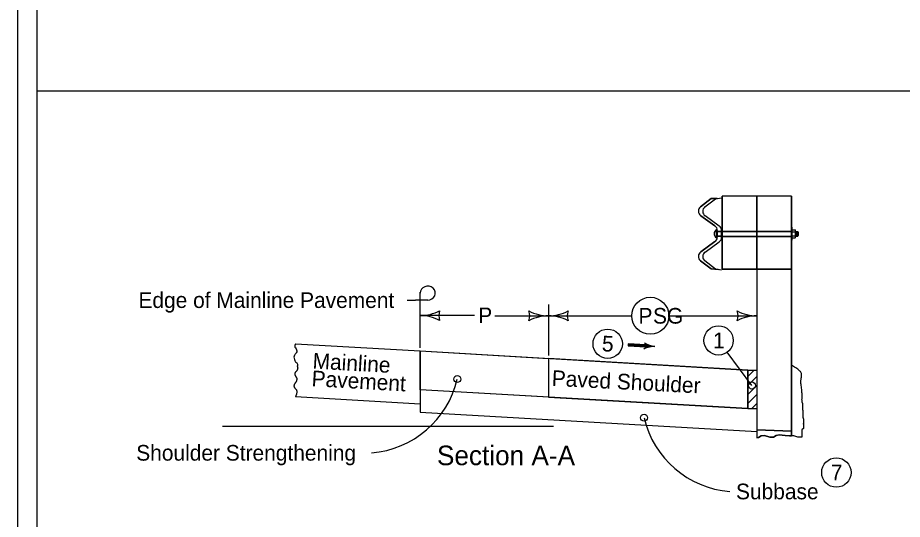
# Model space of a CAD drawing. Extents: x 10133 to 81668, y 7924 to 12229.
# Drawn here: x 10133 to 11037, y 8919 to 9431 of the extents above; entities that cross this region are included whole.
import ezdxf

# ---------------------------------------------------------------- set-up
doc = ezdxf.new("R2010")
doc.units = 0
for name, color, linetype in [('Cell', 7, 'Continuous'), ('dsnTextFinalPlan', 7, 'Continuous'), ('Level 1', 7, 'Continuous'), ('Level 12', 7, 'Continuous'), ('Level 4', 7, 'Continuous'), ('Level 5', 7, 'Continuous'), ('Level 6', 7, 'Continuous'), ('SheetBorder', 7, 'Continuous')]:
    doc.layers.add(name, color=color, linetype=linetype)

msp = doc.modelspace()

# ---------------------------------------------------------------- linework, layer by layer
at = {"layer": 'Cell'}
for p, q in [((10831.21, 9229.02), (10845.72, 9218.6)), ((10845.72, 9202.53), (10831.21, 9192.11))]:
    msp.add_line(p, q, dxfattribs=at)
for points in [[(10888.5, 9213.22), (10888.5, 9248.9), (10852.96, 9248.9), (10852.96, 9213.22), (10852.96, 9213.22), (10888.5, 9213.22)], [(10924.05, 9213.22), (10924.05, 9217.22), (10924.05, 9248.9), (10888.5, 9248.9), (10888.5, 9213.22), (10924.05, 9213.22)], [(10835.46, 9237.92), (10835.45, 9237.91), (10846.22, 9246.31), (10848.11, 9246.65), (10841.78, 9246.53), (10831.02, 9238.14)], [(10850.16, 9218.38), (10850.19, 9218.36), (10835.63, 9228.82), (10835.66, 9228.8)], [(10848.11, 9213.97), (10848.11, 9212.89), (10852.56, 9212.89), (10852.56, 9213.75), (10852.56, 9213.75)], [(10852.96, 9212.89), (10852.96, 9208.22), (10852.96, 9208.22), (10888.5, 9208.22), (10888.5, 9212.89), (10852.96, 9212.89), (10852.96, 9212.89)], [(10924.05, 9208.22), (10924.05, 9212.89), (10888.5, 9212.89), (10888.5, 9208.22), (10924.05, 9208.22)], [(10835.66, 9191.89), (10835.63, 9191.87), (10850.19, 9202.33), (10850.16, 9202.31)], [(10852.56, 9206.94), (10852.56, 9206.94), (10852.56, 9208.22), (10848.12, 9208.22), (10848.12, 9207.16), (10848.12, 9208.22), (10848.11, 9208.22), (10848.11, 9207.16)], [(10852.96, 9207.89), (10852.96, 9174.25), (10888.5, 9174.25), (10888.5, 9207.89), (10852.96, 9207.89)], [(10924.05, 9174.25), (10924.05, 9203.89), (10924.05, 9207.89), (10888.5, 9207.89), (10888.5, 9174.25), (10924.05, 9174.25)], [(10831.02, 9182.99), (10841.78, 9174.6), (10848.88, 9173.91), (10846.22, 9174.38), (10835.45, 9182.79), (10835.46, 9182.77)], [(10924.05, 9008.91), (10924.05, 9174.25), (10888.5, 9174.25), (10888.5, 9071.28), (10888.5, 9064.59), (10888.5, 9064.59), (10888.5, 9064.59), (10888.5, 9055.36), (10888.5, 9055.36), (10888.5, 9055.36), (10888.5, 9046.22), (10888.5, 9046.22), (10888.5, 9046.22), (10888.5, 9039.29), (10888.5, 9010.07), (10924.05, 9008.91)], [(10924.05, 9008.91), (10888.5, 9010.07), (10888.5, 9002.02), (10890.31, 9002.27), (10893.07, 9003.86), (10896.36, 9004.39), (10901.97, 9002.8), (10905.68, 9002.58), (10908.33, 9004.39), (10911.41, 9005.02), (10917.66, 9004.28), (10921.9, 9003.86), (10924.05, 9003.86), (10924.05, 9008.91)]]:
    msp.add_lwpolyline(points, dxfattribs=at)
msp.add_lwpolyline([(10852.56, 9212.89), (10848.11, 9212.89), (10848.11, 9209.43), (10848.12, 9210.56), (10848.12, 9208.22), (10852.56, 9208.22)], close=True, dxfattribs=at)
for centre, start, end in [((10834.49, 9233.65), 127.75002, 234.69086), ((10838.94, 9233.43), 127.75002, 234.69086), ((10842.44, 9213.97), 0, 54.69099), ((10846.88, 9213.75), 0, 54.69099), ((10842.44, 9207.16), 305.30901, 0), ((10846.88, 9206.94), 305.30901, 0), ((10834.49, 9187.48), 125.30914, 232.24998), ((10838.94, 9187.26), 125.30914, 232.24998)]:
    msp.add_arc(centre, 5.68, start, end, dxfattribs=at)
at = {"layer": 'dsnTextFinalPlan'}
for p, q in [((10846.22, 9246.31), (10852.56, 9247.43)), ((10924.05, 9248.9), (10852.96, 9248.9)), ((10852.96, 9174.25), (10852.96, 9248.9)), ((10888.5, 9174.25), (10888.5, 9248.9)), ((10924.05, 9248.9), (10924.05, 9003.86)), ((10831.02, 9238.14), (10841.78, 9246.53)), ((10835.45, 9237.91), (10846.22, 9246.31)), ((10841.78, 9246.53), (10848.11, 9246.65)), ((10845.72, 9218.6), (10831.21, 9229.02)), ((10850.19, 9218.36), (10835.63, 9228.82)), ((10847.34, 9206.5), (10847.34, 9214.58)), ((10847.34, 9212.89), (10852.77, 9212.89)), ((10848.12, 9207.16), (10848.11, 9213.97)), ((10848.29, 9212.89), (10852.96, 9212.89)), ((10852.56, 9210.35), (10852.56, 9213.75)), ((10852.96, 9213.22), (10924.05, 9213.22)), ((10852.96, 9212.89), (10924.05, 9212.89)), ((10924.05, 9217.19), (10924.73, 9217.19)), ((10924.73, 9203.86), (10924.73, 9217.19)), ((10924.73, 9214.57), (10927.7, 9214.57)), ((10924.73, 9212.55), (10927.7, 9212.55)), ((10928.06, 9207.5), (10928.06, 9213.56)), ((10928.06, 9212.86), (10930.43, 9212.86)), ((10928.95, 9212.86), (10928.95, 9208.19)), ((10929.69, 9212.86), (10929.69, 9208.19)), ((10930.43, 9212.86), (10930.88, 9212.33)), ((10930.43, 9212.86), (10930.43, 9208.19)), ((10930.88, 9212.33), (10930.88, 9208.73)), ((10831.21, 9192.11), (10845.72, 9202.53)), ((10835.63, 9191.87), (10850.19, 9202.33)), ((10847.34, 9208.22), (10852.96, 9208.22)), ((10848.11, 9207.16), (10848.12, 9210.56)), ((10848.12, 9210.56), (10848.12, 9207.16)), ((10852.56, 9206.94), (10852.56, 9210.35)), ((10852.56, 9210.35), (10852.56, 9206.94)), ((10852.95, 9207.89), (10924.05, 9207.89)), ((10852.96, 9208.22), (10924.05, 9208.22)), ((10924.05, 9203.86), (10924.73, 9203.86)), ((10924.73, 9208.51), (10927.7, 9208.51)), ((10924.73, 9206.49), (10927.7, 9206.49)), ((10928.06, 9208.19), (10930.43, 9208.19)), ((10930.88, 9208.73), (10930.43, 9208.19)), ((10841.78, 9174.6), (10831.02, 9182.99)), ((10846.22, 9174.38), (10835.45, 9182.79)), ((10848.88, 9173.91), (10841.78, 9174.6)), ((10852.56, 9173.26), (10846.22, 9174.38)), ((10888.5, 9174.25), (10852.96, 9174.25)), ((10888.5, 9174.25), (10888.5, 9002.02)), ((10416.65, 9098.18), (10544.11, 9090.77)), ((10544.11, 9090.77), (10544.11, 9036.76)), ((10544.11, 9090.77), (10879.25, 9071.28)), ((10675.49, 9083.13), (10675.49, 9043.6)), ((10879.25, 9071.28), (10675.49, 9083.13)), ((10675.49, 9083.13), (10675.49, 9043.6)), ((10879.25, 9064.54), (10885.99, 9071.28)), ((10879.25, 9064.54), (10885.99, 9071.28)), ((10879.25, 9064.54), (10885.99, 9071.28)), ((10879.25, 9064.54), (10885.99, 9071.28)), ((10879.25, 9071.28), (10888.49, 9071.28)), ((10879.25, 9071.28), (10879.25, 9031.85)), ((10879.25, 9031.85), (10879.25, 9071.28)), ((10879.25, 9055.35), (10888.49, 9064.59)), ((10879.25, 9055.35), (10888.49, 9064.59)), ((10879.25, 9055.35), (10888.49, 9064.59)), ((10879.25, 9055.35), (10888.49, 9064.59)), ((10934.1, 9064.52), (10934.1, 9064.52)), ((10879.25, 9031.85), (10544.11, 9051.17)), ((10879.25, 9046.13), (10888.49, 9055.36)), ((10879.25, 9046.13), (10888.49, 9055.36)), ((10879.25, 9046.13), (10888.49, 9055.36)), ((10879.25, 9046.13), (10888.49, 9055.36)), ((10416.68, 9044.17), (10544.11, 9036.76)), ((10675.49, 9043.6), (10879.25, 9031.85)), ((10879.25, 9036.9), (10888.49, 9046.14)), ((10544.11, 9036.76), (10544.11, 9028.34)), ((10879.25, 9031.85), (10888.49, 9031.85)), ((10883.35, 9031.85), (10888.49, 9036.99)), ((10544.11, 9028.34), (10888.5, 9008.48)), ((10342.06, 9013.93), (10680.56, 9013.93))]:
    msp.add_line(p, q, dxfattribs=at)
for points in [[(10927.76, 9212.55), (10927.83, 9212.59), (10927.91, 9212.7), (10927.99, 9212.92), (10928.05, 9213.2), (10928.05, 9211.26), (10927.99, 9211.77), (10927.94, 9212.14), (10927.82, 9212.46), (10927.76, 9212.55), (10927.82, 9212.56), (10927.92, 9212.7), (10928.01, 9212.93), (10928.03, 9213.08), (10928.03, 9211.55), (10927.96, 9212.04), (10927.9, 9212.3), (10927.8, 9212.53), (10927.83, 9212.54), (10927.97, 9212.76), (10928.01, 9212.91), (10928.01, 9211.8), (10927.82, 9212.52), (10927.99, 9212.79), (10927.99, 9211.94), (10927.85, 9212.5), (10927.97, 9212.72), (10927.98, 9212.08), (10927.87, 9212.49), (10927.96, 9212.66), (10927.96, 9212.25), (10927.89, 9212.47), (10927.94, 9212.59), (10927.94, 9212.38), (10927.91, 9212.46), (10927.92, 9212.5)], [(10928.05, 9207.82), (10928, 9208.09), (10927.96, 9208.26), (10927.87, 9208.42), (10927.75, 9208.51), (10927.83, 9208.61), (10927.91, 9208.83), (10927.97, 9209.14), (10928.05, 9209.89), (10928.05, 9207.82), (10928.03, 9207.96), (10927.99, 9208.17), (10927.91, 9208.39), (10927.79, 9208.5), (10927.83, 9208.58), (10927.89, 9208.73), (10927.99, 9209.23), (10928.03, 9209.61), (10928.03, 9208.01), (10928, 9208.13), (10927.96, 9208.29), (10927.83, 9208.5), (10927.88, 9208.67), (10927.96, 9209), (10928.02, 9209.33), (10928.01, 9208.16), (10927.97, 9208.29), (10927.86, 9208.49), (10927.9, 9208.7), (10927.96, 9208.96), (10927.99, 9209.13), (10927.99, 9208.27), (10927.93, 9208.38), (10927.88, 9208.49), (10927.97, 9208.95), (10927.97, 9208.35), (10927.9, 9208.49), (10927.95, 9208.78), (10927.95, 9208.43), (10927.92, 9208.5), (10927.93, 9208.6), (10927.93, 9208.52)], [(10934.57, 9040.67), (10934.51, 9040.4), (10934.51, 9040.21), (10934.51, 9040.01), (10934.51, 9039.82), (10934.51, 9039.62), (10934.51, 9039.43), (10934.51, 9039.13), (10934.51, 9038.94), (10934.61, 9038.64), (10934.71, 9038.35), (10934.9, 9038.16), (10934.9, 9037.96), (10935, 9037.76), (10935, 9037.57), (10935, 9037.37), (10935.1, 9037.28), (10935.1, 9037.08), (10935.1, 9036.89), (10935.1, 9036.69), (10935.1, 9036.49), (10935.1, 9036.3), (10935.1, 9036.01), (10935.1, 9035.71), (10935.1, 9035.52), (10935.1, 9035.22), (10935.1, 9035.03), (10935.1, 9034.83), (10935.2, 9034.74), (10935.2, 9034.54), (10935.2, 9034.34), (10935.2, 9034.15), (10935.2, 9033.95), (10935.2, 9033.76), (10935.2, 9033.56), (10935.2, 9033.37), (10935.2, 9033.17), (10935.2, 9032.98), (10935.2, 9032.78), (10935.2, 9032.59), (10935.2, 9032.39), (10935.2, 9032.2), (10935.2, 9032), (10935.2, 9031.8), (10935.2, 9031.61), (10935.2, 9031.41), (10935.2, 9031.22), (10935.29, 9031.12), (10935.29, 9030.93), (10935.29, 9030.73), (10935.39, 9030.63), (10935.39, 9030.44), (10935.39, 9030.24), (10935.49, 9030.14), (10935.49, 9029.95), (10935.49, 9029.75), (10935.49, 9029.56), (10935.49, 9029.26), (10935.59, 9028.97), (10935.59, 9028.78), (10935.59, 9028.58), (10935.59, 9028.38), (10935.59, 9028.19), (10935.59, 9027.99), (10935.59, 9027.8), (10935.59, 9027.6), (10935.59, 9027.41), (10935.59, 9027.21), (10935.59, 9027.02), (10935.59, 9026.82), (10935.59, 9026.63), (10935.59, 9026.43), (10935.59, 9026.24), (10935.59, 9026.04), (10935.59, 9025.84), (10935.59, 9025.65), (10935.59, 9025.45), (10935.59, 9025.26), (10935.59, 9025.06), (10935.59, 9024.87), (10935.59, 9024.67), (10935.59, 9024.48), (10935.59, 9024.28), (10935.59, 9024.09), (10935.59, 9023.89), (10935.59, 9023.69), (10935.59, 9023.5), (10935.59, 9023.3), (10935.68, 9023.21), (10935.68, 9022.91), (10935.68, 9022.72), (10935.78, 9022.52), (10935.88, 9022.23), (10935.88, 9022.03), (10935.98, 9021.94), (10935.98, 9021.74), (10936.07, 9021.64), (10936.17, 9021.55), (10936.17, 9021.35), (10936.17, 9021.15), (10936.17, 9020.96), (10936.27, 9020.86), (10936.27, 9020.67), (10936.27, 9020.47), (10936.27, 9020.28), (10936.27, 9020.08), (10936.27, 9019.88), (10936.27, 9019.69), (10936.27, 9019.49), (10936.27, 9019.3), (10936.27, 9019.1), (10936.27, 9018.91), (10936.27, 9018.71), (10936.27, 9018.52), (10936.27, 9018.32), (10936.27, 9018.13), (10936.27, 9017.93), (10936.27, 9017.73), (10936.27, 9017.54), (10936.27, 9017.34), (10936.27, 9017.15), (10936.27, 9016.95), (10936.27, 9016.76), (10936.27, 9016.56), (10936.27, 9016.37), (10936.27, 9016.17), (10936.27, 9015.98), (10936.27, 9015.98), (10936.27, 9016.27), (10936.27, 9016.46), (10936.27, 9016.66), (10936.27, 9016.46), (10936.27, 9016.27), (10936.27, 9016.07), (10936.27, 9015.88), (10936.27, 9015.68), (10936.27, 9015.49), (10936.27, 9015.29), (10936.27, 9015.1), (10936.27, 9014.9), (10936.27, 9014.71), (10936.27, 9014.51), (10936.27, 9014.32), (10936.27, 9014.12), (10936.27, 9013.92), (10936.27, 9013.73), (10936.17, 9013.63), (10936.17, 9013.44), (10936.17, 9013.24), (10936.17, 9013.05), (10936.17, 9012.85), (10936.17, 9012.65), (10936.17, 9012.46), (10936.17, 9012.26), (10936.17, 9012.07), (10936.17, 9011.87), (10936.17, 9011.68), (10936.07, 9011.58), (10935.98, 9011.38), (10935.88, 9011.29), (10935.78, 9011.19), (10935.68, 9011.09), (10935.49, 9010.99), (10935.29, 9010.99), (10935.2, 9010.9), (10935.1, 9010.8), (10935, 9010.7), (10934.8, 9010.6), (10934.71, 9010.5), (10934.71, 9010.31), (10934.61, 9010.21), (10934.61, 9010.02), (10934.61, 9009.82), (10934.61, 9009.63), (10934.61, 9002.81)], [(10934.74, 9002.81), (10930.59, 9002.69), (10926.46, 9003.86), (10921.9, 9003.86), (10917.66, 9004.28), (10911.41, 9005.02), (10908.33, 9004.39), (10905.68, 9002.58), (10901.97, 9002.8), (10896.36, 9004.39), (10893.07, 9003.86), (10890.31, 9002.27), (10888.5, 9002.02)]]:
    msp.add_lwpolyline(points, dxfattribs=at)
msp.add_lwpolyline([(10675.49, 9043.6), (10544.11, 9051.17), (10544.11, 9090.77), (10675.49, 9083.13)], close=True, dxfattribs=at)
for centre, radius, start, end in [((10834.49, 9233.65), 5.68, 127.75002, 234.69086), ((10838.94, 9233.43), 5.68, 127.75002, 234.69086), ((10849.42, 9210.55), 4.54, 117.20289, 242.8461), ((10842.44, 9213.97), 5.68, 360, 54.69099), ((10846.88, 9213.75), 5.68, 360, 54.69099), ((10842.44, 9207.16), 5.68, 305.30901, 0), ((10846.88, 9206.94), 5.68, 305.30901, 0), ((10834.49, 9187.48), 5.68, 125.30914, 232.24998), ((10838.94, 9187.26), 5.68, 125.30914, 232.24998)]:
    msp.add_arc(centre, radius, start, end, dxfattribs=at)
for centre in [(10927.7, 9213.56), (10927.7, 9207.5)]:
    msp.add_ellipse(centre, major_axis=(0, -1.01), ratio=0.362258, start_param=6.283156, end_param=9.424748, dxfattribs=at)
for points in [[(10416.65, 9098.18), (10416.15, 9094.58), (10417.19, 9093.08), (10418.05, 9090.78), (10417.45, 9088.72), (10415.54, 9086.34), (10415.02, 9084.44), (10415.54, 9082.15), (10416.41, 9079.77), (10417.45, 9079.06), (10418.83, 9076.52), (10418.82, 9075.69)], [(10416.86, 9058.57), (10417.07, 9058.82), (10417.27, 9059.08), (10417.62, 9059.64), (10417.9, 9060.23), (10418.02, 9060.54), (10418.12, 9060.85), (10418.25, 9061.47), (10418.3, 9062.09), (10418.25, 9062.68), (10418.19, 9062.96), (10418.16, 9063.09), (10418.11, 9063.22), (10417.9, 9063.6), (10417.62, 9063.96), (10417.32, 9064.33), (10417.07, 9064.73), (10416.93, 9065.01), (10416.79, 9065.29), (10416.53, 9065.87), (10416.33, 9066.44), (10416.26, 9066.73), (10416.2, 9067.02), (10416.19, 9067.15), (10416.19, 9067.28), (10416.34, 9068.06), (10416.55, 9068.57), (10416.81, 9069.08), (10417.25, 9069.72), (10417.77, 9070.27), (10418.29, 9070.81), (10418.52, 9071.12), (10418.72, 9071.46), (10418.92, 9071.93), (10419.08, 9072.41), (10419.18, 9072.88), (10419.22, 9073.12), (10419.23, 9073.24), (10419.24, 9073.36), (10419.19, 9073.87), (10419.04, 9074.38), (10418.99, 9074.51), (10418.93, 9074.64), (10418.88, 9074.76), (10418.86, 9074.9), (10418.82, 9075.69)], [(10934.57, 9040.67), (10934.89, 9043.58), (10934.67, 9048.45), (10934.23, 9054.2), (10933.56, 9058.62), (10933.78, 9061.93), (10934.23, 9066.13), (10933.56, 9069.23), (10931.35, 9071.22), (10929.36, 9072.99), (10927.15, 9074.1), (10924.94, 9075.42), (10924.06, 9076.09)], [(10416.86, 9058.57), (10416.64, 9058.34), (10416.4, 9058.1), (10416.16, 9057.86), (10415.98, 9057.59), (10415.84, 9057.31), (10415.7, 9057.02), (10415.44, 9056.45), (10415.33, 9056.17), (10415.23, 9055.88), (10415.16, 9055.59), (10415.13, 9055.44), (10415.11, 9055.3), (10415.12, 9054.78), (10415.25, 9054.26), (10415.46, 9053.75), (10415.72, 9053.24), (10416.16, 9052.6), (10416.68, 9052.05), (10417.2, 9051.51), (10417.43, 9051.2), (10417.63, 9050.86), (10418.03, 9049.91), (10418.14, 9049.44), (10418.15, 9048.96), (10418.11, 9048.67), (10418.06, 9048.38), (10418.01, 9048.1), (10417.94, 9047.81), (10417.63, 9046.66), (10417.45, 9046.05), (10417.25, 9045.45), (10417.03, 9044.86), (10416.9, 9044.57), (10416.76, 9044.29), (10416.68, 9044.17)]]:
    msp.add_spline(points, degree=3, dxfattribs=at)
at = {"layer": 'Level 1'}
msp.add_line((10152.18, 9924.36), (10152.18, 8314.36), dxfattribs=at)
at = {"layer": 'Level 12'}
for centre, radius in [((10735.98, 9098.17), 15), ((10849.44, 9101.57), 15), ((10883.56, 9055.46), 3.58), ((10969.88, 8966.52), 15)]:
    msp.add_circle(centre, radius, dxfattribs=at)
at = {"layer": 'Level 4'}
for p, q in [((12307.76, 9356.36), (10152.18, 9356.36)), ((10883.56, 9055.46), (10858.18, 9089.38))]:
    msp.add_line(p, q, dxfattribs=at)
for centre in [(10582.12, 9062.01), (10773.25, 9022.49)]:
    msp.add_circle(centre, 3.54, dxfattribs=at)
at = {"layer": 'Level 5'}
for p, q in [((10675.49, 9138.3), (10675.49, 9086.27)), ((10599.61, 9126.91), (10544.13, 9126.91)), ((10620.73, 9126.69), (10675.49, 9126.69)), ((10675.49, 9126.69), (10760.66, 9126.69)), ((10798.53, 9126.69), (10888.5, 9126.69))]:
    msp.add_line(p, q, dxfattribs=at)
msp.add_circle((10779.6, 9126.69), 18.93, dxfattribs=at)
for centre, radius, start, end in [((10544.13, 9169.41), 42.5, 270, 298.07249), ((10579.77, 9126.91), 16.42, 162.26665, 197.73335), ((10639.85, 9126.69), 16.42, 342.26665, 17.73335), ((10675.49, 9169.19), 42.5, 241.92751, 270), ((10675.49, 9169.19), 42.5, 270, 298.07249), ((10711.12, 9126.69), 16.42, 162.26665, 197.73335), ((10852.87, 9126.69), 16.42, 342.26665, 17.73335), ((10888.5, 9169.19), 42.5, 241.92751, 270), ((10544.13, 9084.41), 42.5, 61.92751, 90), ((10675.49, 9084.19), 42.5, 90, 118.07249), ((10675.49, 9084.19), 42.5, 61.92751, 90), ((10888.5, 9084.19), 42.5, 90, 118.07249), ((10486.89, 9084.13), 97.76, 274.44201, 346.92302), ((10868.48, 9044.61), 97.76, 193.07698, 265.55799)]:
    msp.add_arc(centre, radius, start, end, dxfattribs=at)
at = {"layer": 'Level 6'}
for p, q in [((10544.11, 9129.85), (10544.11, 9150.71)), ((10530.74, 9142.7), (10539.43, 9142.7)), ((10551.92, 9142.7), (10539.43, 9142.7)), ((10544.11, 9093.91), (10544.11, 9129.85)), ((10775.08, 9095.94), (10756.88, 9096.99)), ((10774.98, 9095.01), (10774.98, 9095.01)), ((10775.09, 9096.95), (10775.09, 9096.95))]:
    msp.add_line(p, q, dxfattribs=at)
for points in [[(10775.11, 9096.89), (10756.94, 9097.94), (10756.81, 9096.05), (10774.98, 9095.01), (10775.03, 9096.62), (10757.16, 9097.71), (10757.1, 9096.21), (10774.6, 9095.27), (10774.72, 9096.39), (10757.39, 9097.45), (10757.37, 9096.45), (10774.38, 9095.47), (10774.48, 9096.17), (10757.58, 9097.23), (10757.57, 9096.67), (10774.17, 9095.73)], [(10774.7, 9098.14), (10775.4, 9096.97), (10775.38, 9095.33), (10774.62, 9093.93), (10777.37, 9094.79), (10780.57, 9095.45), (10781.47, 9095.58), (10779.22, 9096.13), (10776, 9097.36), (10775.05, 9097.89), (10775.17, 9094.38), (10780.12, 9095.6), (10775.48, 9097.18), (10775.5, 9094.76), (10778.89, 9095.69), (10775.89, 9096.55), (10775.66, 9095.16), (10777.82, 9095.67), (10776.23, 9096.18), (10776.1, 9095.52), (10776.88, 9095.68)]]:
    msp.add_lwpolyline(points, dxfattribs=at)
for centre, major_axis, start_param, end_param in [((10551.92, 9149.83), (-7.81, 0), 1.570796, 6.283185), ((10771.31, 9096.16), (3.88, 0), 5.202895, 7.237436), ((10783.58, 9075.16), (22.17, 0), 1.537172, 2.061295), ((10786.37, 9115.58), (-22.17, 0), 0.954258, 1.478381)]:
    msp.add_ellipse(centre, major_axis=major_axis, ratio=0.913811, start_param=start_param, end_param=end_param, dxfattribs=at)
at = {"layer": 'SheetBorder'}
msp.add_lwpolyline([(10132.52, 9944.02), (13267.53, 9944.02), (13267.53, 7924.02), (10132.52, 7924.02)], close=True, dxfattribs=at)

# ---------------------------------------------------------------- texts
at = {"layer": 'Level 12'}
msp.add_text('5', height=16, rotation=356.69973, dxfattribs=at).set_placement((10729.76, 9090.52))
for s, p in [('1', (10843.82, 9093.57)), ('7', (10964.18, 8958.52))]:
    msp.add_text(s, height=16, dxfattribs=at).set_placement(p)
at = {"layer": 'Level 5'}
for s, p in [('P', (10603.61, 9119.17)), ('P', (10767.47, 9118.69)), ('SG', (10782.38, 9118.69))]:
    msp.add_text(s, height=16, dxfattribs=at).set_placement(p)
at = {"layer": 'Level 6'}
for s, height, p in [('Edge of Mainline Pavement', 16, (10256.04, 9134.7)), ('Shoulder Strengthening', 16, (10253.79, 8978.66)), ('Section A-A', 20, (10561.37, 8974)), ('Subbase', 16, (10867.26, 8939.14))]:
    msp.add_text(s, height=height, dxfattribs=at).set_placement(p)
for s, rotation, p in [('Mainline', 356.73462, (10433.87, 9072.84)), ('Pavement', 356.73462, (10432.84, 9054.87)), ('Paved Shoulder ', 357.0678, (10678.51, 9055.18))]:
    msp.add_text(s, height=16, rotation=rotation, dxfattribs=at).set_placement(p)

doc.saveas('drawing.dxf')
